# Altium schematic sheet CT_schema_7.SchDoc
size 254 x 194 mm
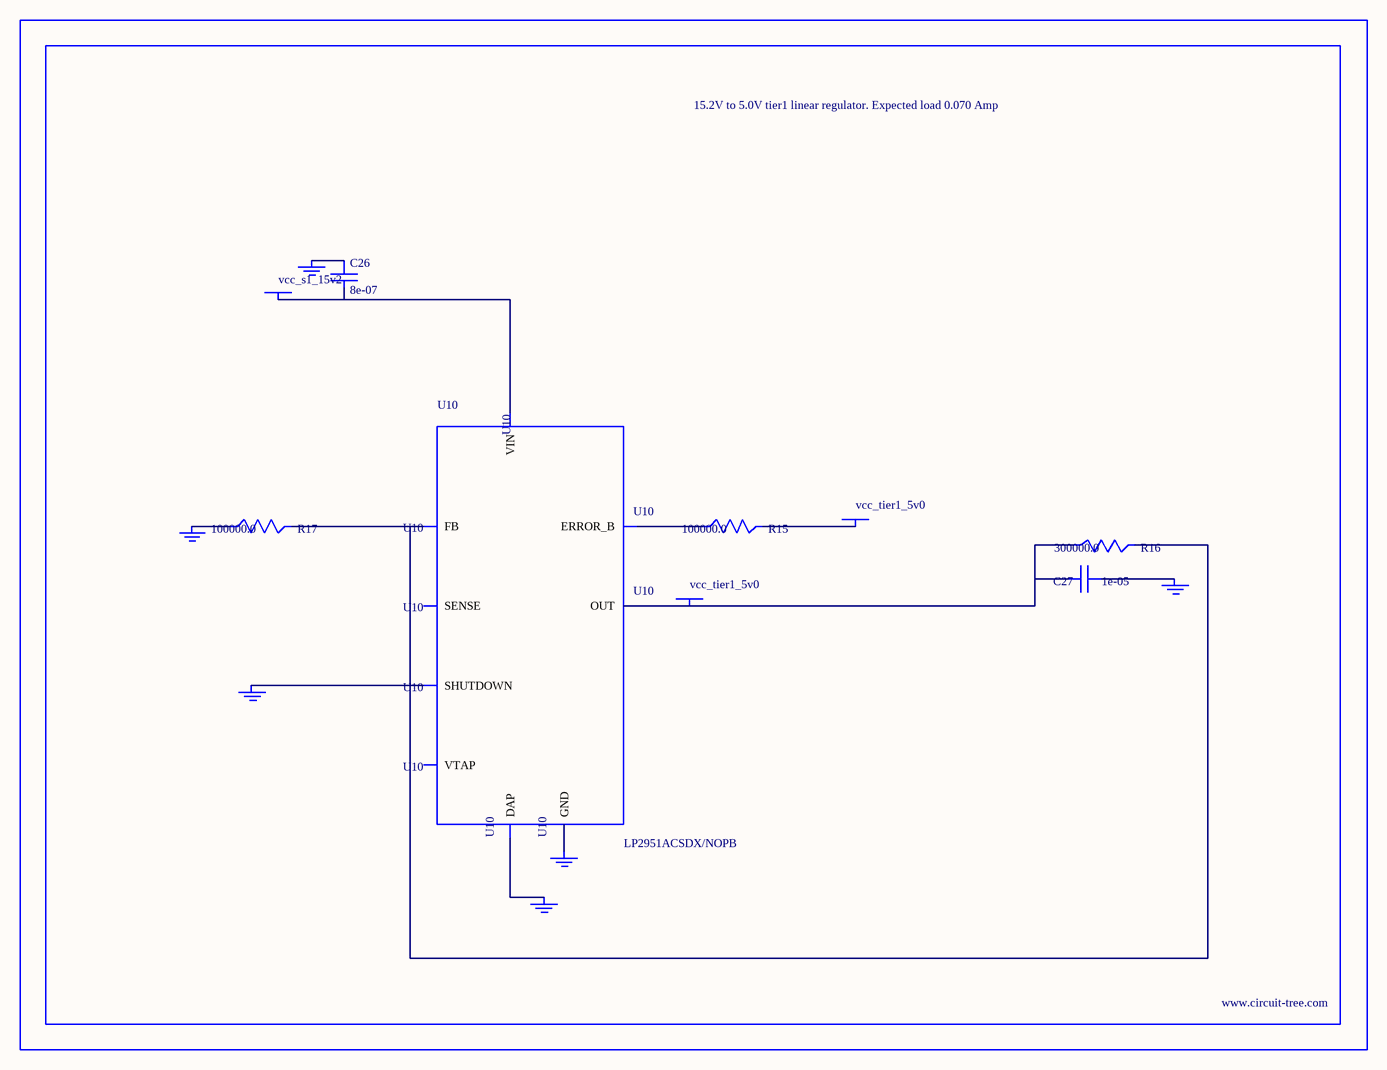
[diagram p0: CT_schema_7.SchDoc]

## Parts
BORDER6  (no value)
C26  8e-07  [R0603]
C27  1e-05  [C1210]
GND_INSTANCE_6_0  (no value)
GND_INSTANCE_6_1  (no value)
GND_INSTANCE_6_2  (no value)
GND_INSTANCE_6_3  (no value)
GND_INSTANCE_6_4  (no value)
GND_INSTANCE_6_5  (no value)
POWER_INSTANCE_6_0  vcc_tier1_5v0
POWER_INSTANCE_6_1  vcc_s1_15v2
POWER_INSTANCE_6_2  vcc_tier1_5v0
R15  100000.0  [R0603]
R16  300000.0  [R0603]
R17  100000.0  [R0603]
U10  LP2951ACSDX/NOPB  [WSON-8]

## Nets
NetC26_1: C26.1 GND_INSTANCE_6_3.0(GND)
NetC26_2: C26.2 POWER_INSTANCE_6_1.0(PWR) U10.8(VIN)
NetC27_1: C27.1 GND_INSTANCE_6_0.0(GND)
NetC27_2: C27.2 POWER_INSTANCE_6_2.0(PWR) R16.1 U10.1(OUT)
NetGND_INSTANCE_6_1_0: GND_INSTANCE_6_1.0(GND) U10.3(SHUTDOWN)
NetGND_INSTANCE_6_2_0: GND_INSTANCE_6_2.0(GND) R17.1
NetGND_INSTANCE_6_4_0: GND_INSTANCE_6_4.0(GND) U10.PAD(DAP)
NetGND_INSTANCE_6_5_0: GND_INSTANCE_6_5.0(GND) U10.4(GND)
NetPOWER_INSTANCE_6_0_0: POWER_INSTANCE_6_0.0(PWR) R15.2
NetR15_1: R15.1 U10.5(ERROR_B)
NetR16_2: R16.2 R17.2 U10.7(FB)

Not connected (* = marked no-connect by the designer): U10 2(SENSE) 6(VTAP)

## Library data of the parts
BORDER6 = BORDER_PAGE6
C26 = C26
C27 = GRM32DR61E106MA12L
GND_INSTANCE_6_0-GND_INSTANCE_6_5 = GND
POWER_INSTANCE_6_0-POWER_INSTANCE_6_2 = PWR
R15 R17 = RC0603JR-07100KL
R16 = RC0603JR-07300KL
